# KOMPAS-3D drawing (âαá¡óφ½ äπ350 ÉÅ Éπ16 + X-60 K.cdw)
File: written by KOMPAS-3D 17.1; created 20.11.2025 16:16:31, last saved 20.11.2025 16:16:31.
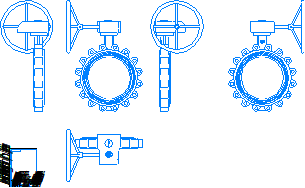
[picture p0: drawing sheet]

Sheet 1: A4, portrait

Title block, sheet 1: name: Гранвэл Ду350; material: Сталь 10  ГОСТ 1050-88; mass: 216,58; sheets: 1; sheet format: A4

Views: Вид 1, Спереди, Проекционный вид 2, Проекционный вид 3, Проекционный вид 4, Проекционный вид 5
Referenced files in \\adlc.lan\data\АДЛ_ПКД\3D-модели\ADL production\Дисковые поворотные затворы ГРАНВЭЛ\с резьбовыми проушинами с китайским редуктором Ру 16\KOMPAS 3D\: Гранвэл Ду350 РП Ру16 + X-60 K.m3d
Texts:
  Andrey
  АДЛ
Dimensions and other numbers on the sheet: 1:1; 1; 216,58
